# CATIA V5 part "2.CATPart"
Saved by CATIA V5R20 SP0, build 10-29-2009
Part number: 2
Bounding box of the stored display mesh (mm): x -44 to 43.999, y -43.999 to 44, z -130 to 75.817
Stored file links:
  E:\Ehsan\Amoozesh\CATIA\CATIA Course\Advanced\Videos\Session-24\2.CATPart
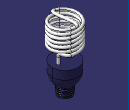
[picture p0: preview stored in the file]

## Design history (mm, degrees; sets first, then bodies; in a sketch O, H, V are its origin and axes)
AxisSystem1: origin (0, 0, 0), X (1, 0, 0), Y (0, 1, 0), Z (0, 0, 1)
Set1
  Circle1: type CtrRad, Start 0, End 180, Radius 40, Center vertex [YZ plane of AxisSystem1 | ZX plane of AxisSystem1 | XY plane of AxisSystem1], Support XY plane of AxisSystem1, FirstDirection (1, 0, 0)
  Set2
    Point1: type OnCurve, Support Circle1, RefPoint {extremum Reference Circle1, Direction (1, 2, 3)}, Length 0
    Point2: type OnCurve, Support Circle1, RefPoint {extremum Reference Circle1, Direction (1, 2, 3)}, Length 125.6637 {= length(Circle1) / 2}
  Helix1: Direction edge [ZX plane of AxisSystem1 | YZ plane of AxisSystem1], RefPoint Point2, Pitch 23, Height 70, TaperAngle 0
  Helix2: Direction edge [ZX plane of AxisSystem1 | YZ plane of AxisSystem1], RefPoint Point1, Pitch 23, Height 70, TaperAngle 0
  Point3: (20, 0, -20), in AxisSystem1
  Point4: (-20, 0, -20), in AxisSystem1
  Line1: type PtDir, RefPoint Point3, Direction edge [ZX plane of AxisSystem1 | YZ plane of AxisSystem1], Start 0, End 25
  Line2: type PtDir, RefPoint Point4, Direction edge [ZX plane of AxisSystem1 | YZ plane of AxisSystem1], Start 0, End 25
  Curve1: Elements the part
  Curve2: Elements the part
  Curve3: Elements the part
  Join1: Elements (Line1; Curve3; Helix2; Curve1; Helix1; Curve2; Line2)
  Sweep1: type Circle, Guide Join1, Radius 4
  Translate1: ToTransfor Circle1, Direction edge [ZX plane of AxisSystem1 | YZ plane of AxisSystem1], Length -40
  Fill1: Boundary Translate1
  Extrude1: Lim1 0, Lim2 26, Direction XY plane of AxisSystem1, Element1 Translate1
  Point5: type Center, Curve edge of Extrude1
  Sphere1: Center Point5, Axis AxisSystem1, Radius 40, Angle1 -90, Angle3 -180, Angle4 180
  Translate2: ToTransfor Translate1, Direction XY plane of AxisSystem1, Length -40
  Point6: type Center, Curve Translate2
  Circle2: type CtrRad, Start 0, End 180, Radius 20, Center Point6, Support xy-plane, FirstDirection (1, 0, 0)
  Extrude2: Lim1 0, Lim2 50, Direction (0, 0, 1), Element1 Circle2
  Trim1: Trimmed (Extrude2; Sphere1)
  Fill2: Boundary edge of Extrude2
  Trim2: Trimmed (Sweep1; Fill1)
  Join2: Elements (Trim2; Extrude1; Trim1; Fill2)
  ThickSurface1: Surface Join2, TopOffset 1, BotOffset 0
  Point7: type OnCurve, Support edge [face of ThickSurface1 | face of ThickSurface1], Length 0
  Helix3: Direction Z axis, RefPoint Point7, Pitch 5, Height 27, TaperAngle 0
  Plane1: type Normal, Curve Helix3, RefPoint Point7
  Sketch1 on Plane1, origin (0, 3.973, -0.7884), H (-1, 0, 0), V (0, 0.0398, 0.9992)
    circle A1 centre (20, -99.9316) radius 1.5
    reference projected point E1 (20, -99.9316) from Point7
    radius A1 = 1.5
    concentricity: A1 E1
  Sweep2: type Unspec, Profile Sketch1, Guide Helix3
  Add1: tool Sweep2
  Fillet1: radius 1, on edge [face of Sweep2 | face of Sweep2]; face of Sweep2
Body1 (main body)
